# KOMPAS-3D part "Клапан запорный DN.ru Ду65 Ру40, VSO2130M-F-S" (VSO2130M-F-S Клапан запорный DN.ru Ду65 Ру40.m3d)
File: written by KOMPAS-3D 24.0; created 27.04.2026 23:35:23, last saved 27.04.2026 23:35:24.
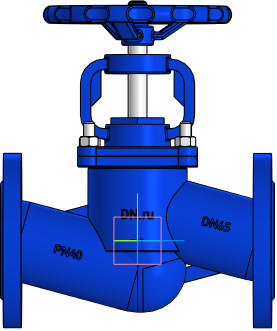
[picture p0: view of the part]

Document properties: Автор: DN.ru; Полное имя файла: C:\Работа\ГОТОВЫЕ ИСХОДНИКИ\VSO2130M-F-S Клапан запорный сальниковый DN.ru Ду15-100 Ру40\DN65\VSO2130M-F-S Клапан запорный DN.ru Ду65 Ру40.m3d

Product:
- Part/product: Клапан запорный DN.ru Ду65 Ру40  | designation VSO2130M-F-S
    Масса: 24
    Раздел спецификации: Прочие изделия
    Примечание: D090-01985

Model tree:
1. Операция без истории:1

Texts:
  VSO2130M-F-S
